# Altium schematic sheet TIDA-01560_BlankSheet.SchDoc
size 431 x 279 mm; Date: Not shown in title block; ApprovedBy: Not shown in title block; CheckedBy: Not shown in title block; Author: Not shown in title block; CompanyName: Not shown in title block; Engineer: Not shown in title block; Organization: Not shown in title block; Address1: Not shown in title block; Address2: Not shown in title block; Address3: Not shown in title block; Address4: Not shown in title block; DocumentNumber: 1; Revision: Use project parameter SCH_Rev; SheetNumber: 2; SheetTotal: 2; PageSetup: Record=PageOptions¦CenterHorizontal=True¦CenterVertical=True¦PrintScale=1.00¦XCorrection=1.00¦YCorrection=1.00¦PrintKind=0¦BorderSize=5000000¦LeftOffset=0¦BottomOffset=0¦Orientation=2¦PaperLength=1000¦PaperWidth=1000¦Scale=100¦PaperSource=15¦PrintQuality=600¦MediaType=1¦DitherType=10¦PaperKind=Letter¦PrintScaleMode=1
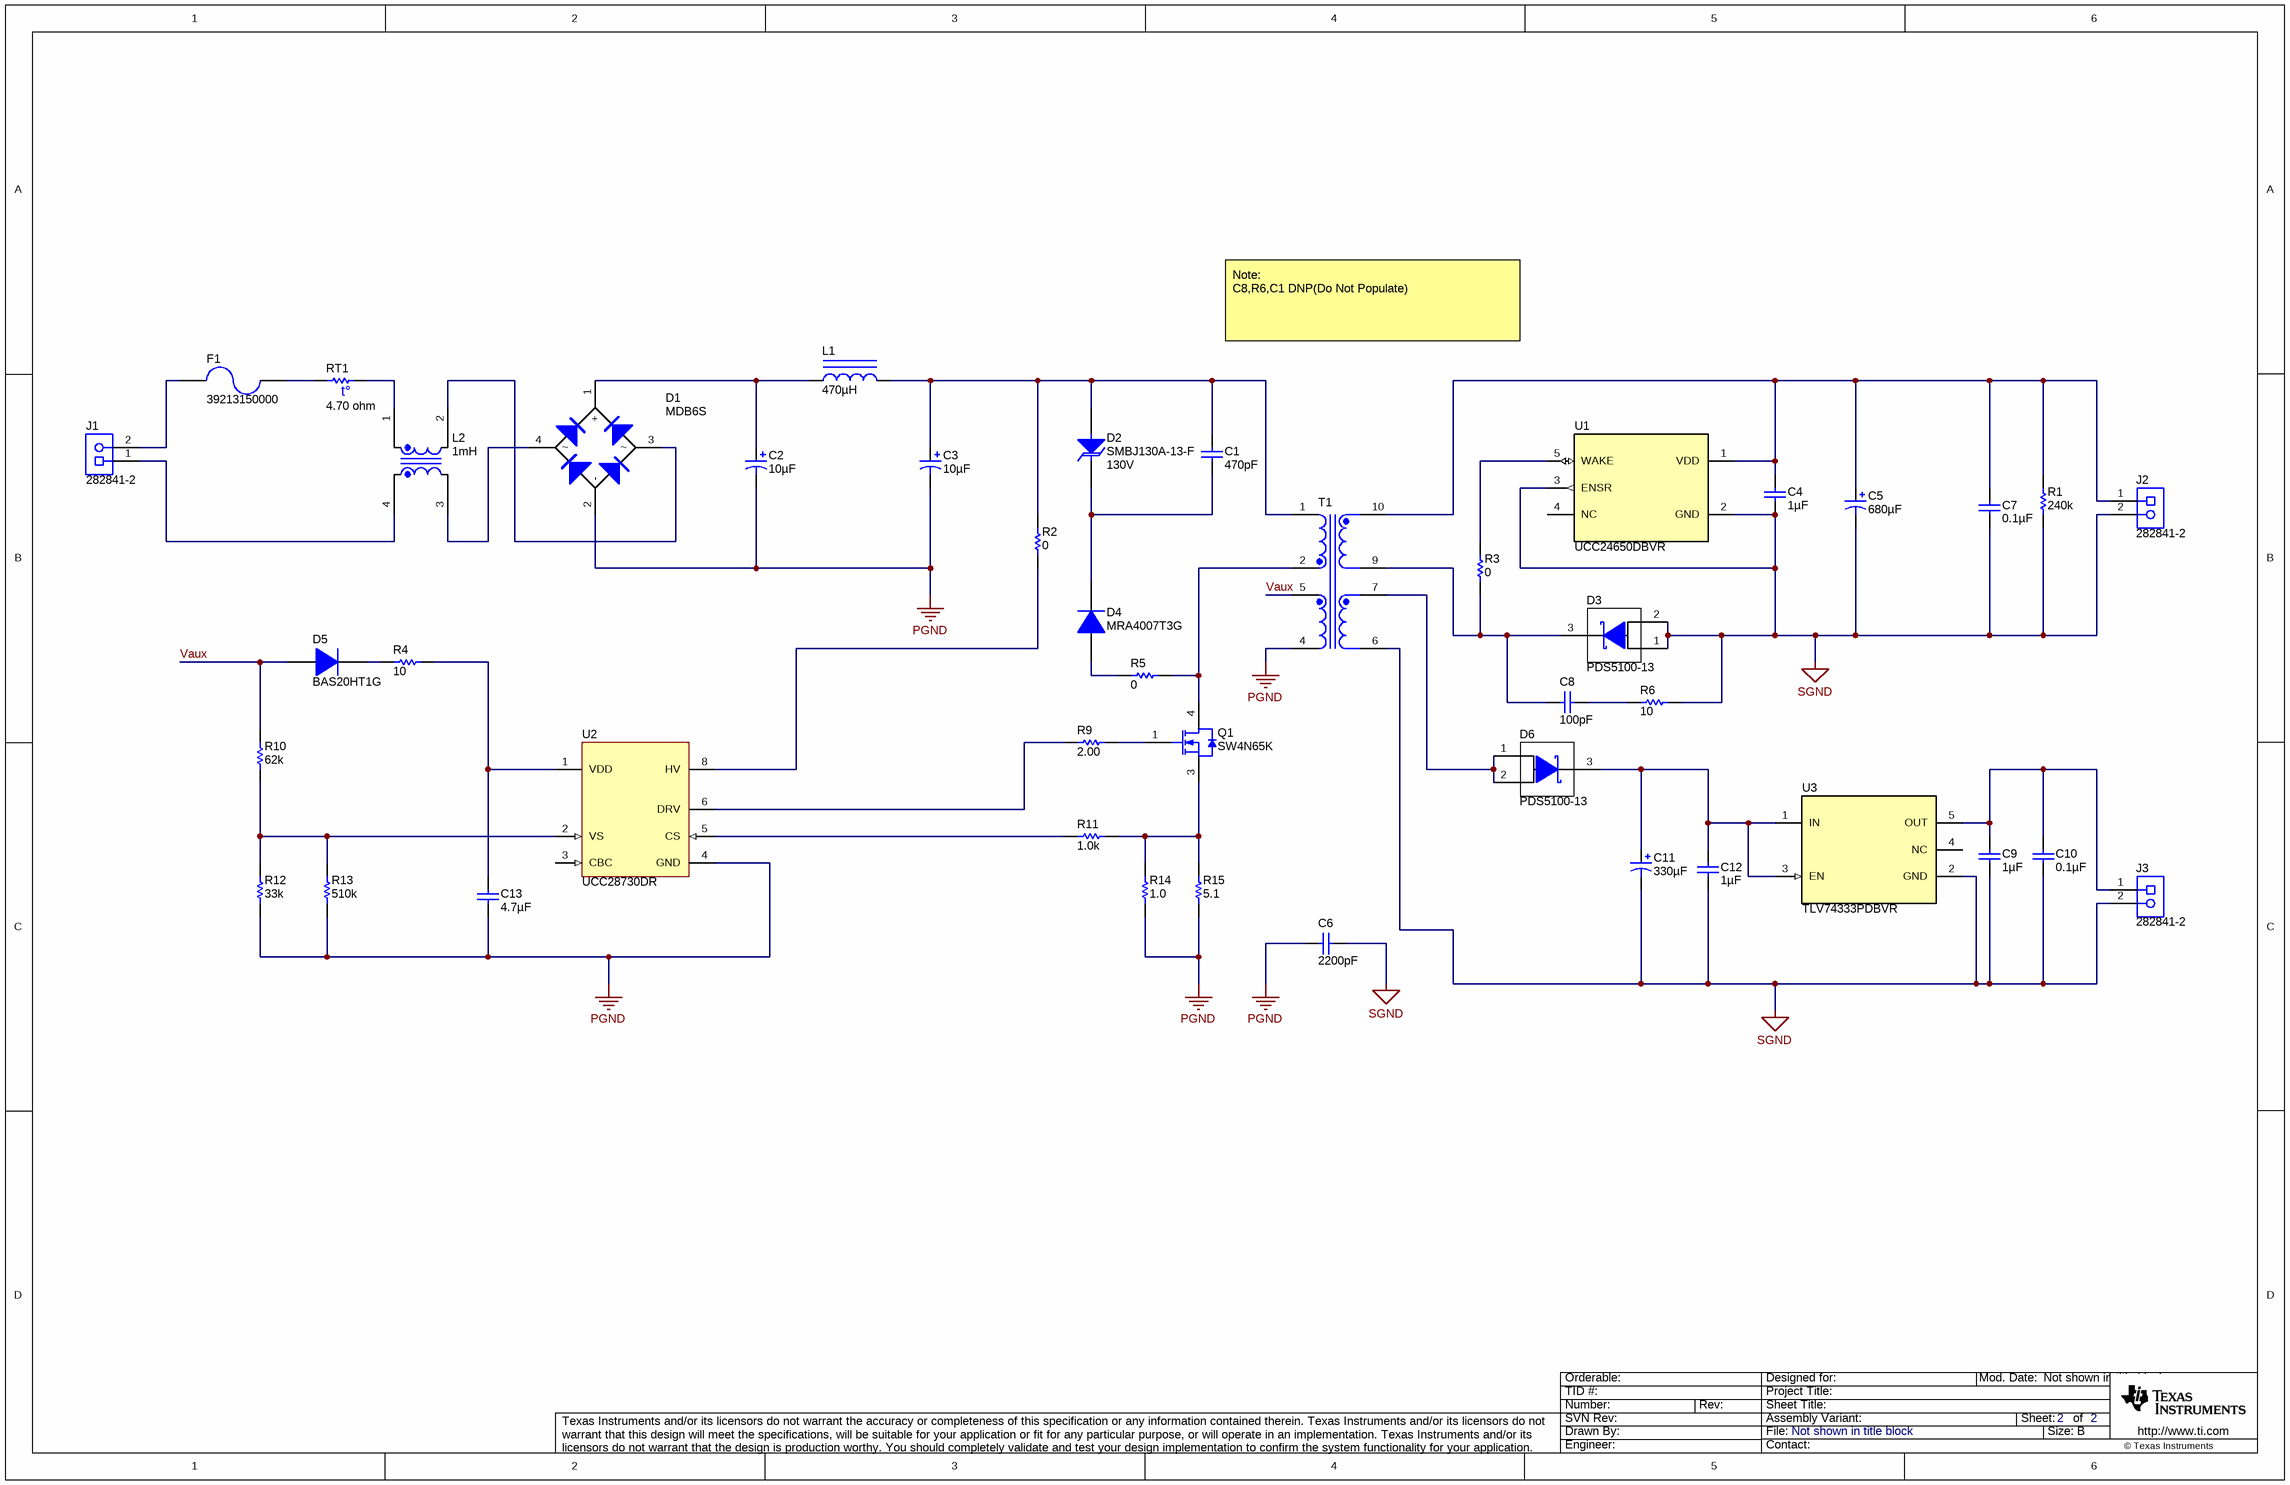
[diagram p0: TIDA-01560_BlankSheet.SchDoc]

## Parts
C1  ValueDisplayed: 470pF  [1206]  (hidden comment: GRM31A7U2J471JW31D)
C2  ValueDisplayed: 10µF  [CY_1000x1600]  (hidden comment: UCY2G100MPD1TD)
C3  ValueDisplayed: 10µF  [CY_1000x1600]  (hidden comment: UCY2G100MPD1TD)
C4  ValueDisplayed: 1µF  [0603]  (hidden comment: 06033C105KAT2A)
C5  ValueDisplayed: 680µF  [R7_1000x1250]  (hidden comment: APSG200ELL681MJB5S)
C6  ValueDisplayed: 2200pF  [KX_1000x800x1400]  (hidden comment: DE1E3KX222MN5AA01)
C7  ValueDisplayed: 0.1µF  [0603]  (hidden comment: C0603C104K3RACTU)
C8  ValueDisplayed: 100pF  [0805_HV]  (hidden comment: GCM2165C2A101JA16D)
C9  ValueDisplayed: 1µF  [0603]  (hidden comment: C1608X7R1E105K080AB)
C10  ValueDisplayed: 0.1µF  [0603]  (hidden comment: C0603C104K3RACTU)
C11  ValueDisplayed: 330µF  [SM_RADIAL_6.3AMM]  (hidden comment: 875105144010)
C12  ValueDisplayed: 1µF  [0603]  (hidden comment: C1608X7R1E105K080AB)
C13  ValueDisplayed: 4.7µF  [1206_180]  (hidden comment: C3216X7R1H475K160AC)
D1  MDB6S  [MICRODIP_4]
D2  SMBJ130A-13-F  value 130V  [SMB]
D3  PDS5100-13  [PowerDI5]
D4  MRA4007T3G  [SMA]
D5  BAS20HT1G  [sod-323]
D6  PDS5100-13  [PowerDI5]
F1  39213150000  [FUSE_392]
J1  282841-2  [TEC_282841-2]
J2  282841-2  [TEC_282841-2]
J3  282841-2  [TEC_282841-2]
L1  ValueDisplayed: 470µH  [WE-TI_5075]  (hidden comment: 7447462471)
L2  ValueDisplayed: 1mH  [WE-CMB_XS]  (hidden comment: 744821201)
Q1  SW4N65K  [TO-252]
R1  ValueDisplayed: 240k  [0805_HV]  (hidden comment: CRCW0805240KJNEA)
R2  ValueDisplayed: 0  [1206]  (hidden comment: CRCW12060000Z0EA)
R3  ValueDisplayed: 0  [0805_HV]  (hidden comment: CRCW08050000Z0EA)
R4  ValueDisplayed: 10  [0805_HV]  (hidden comment: CRCW080510R0JNEA)
R5  ValueDisplayed: 0  [1206]  (hidden comment: CRCW12060000Z0EA)
R6  ValueDisplayed: 10  [1206]  (hidden comment: CRCW120610R0JNEA)
R9  ValueDisplayed: 2.00  [0603]  (hidden comment: CRCW06032R00FKEA)
R10  ValueDisplayed: 62k  [0805_HV]  (hidden comment: CRCW080562K0JNEA)
R11  ValueDisplayed: 1.0k  [0603]  (hidden comment: CRCW06031K00JNEA)
R12  ValueDisplayed: 33k  [0603]  (hidden comment: CRCW060333K0JNEA)
R13  ValueDisplayed: 510k  [0603]  (hidden comment: CRCW0603510KJNEA)
R14  ValueDisplayed: 1.0  [0805_HV]  (hidden comment: CRCW08051R00JNEA)
R15  ValueDisplayed: 5.1  [0805_HV]  (hidden comment: CRCW08055R10JNEA)
RT1  value 4.70 ohm  [S153]  (hidden comment: B57153S0479M051)
T1  750343769,Rev02  [PCBComponent_1]  (value not drawn)
U1  UCC24650DBVR  [DBV0005A_N]
U2  UCC28730DR  [D0007A_N]
U3  TLV74333PDBVR  [DBV0005A_N]

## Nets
PGND: C2.2(-) C3.2(-) C6.2 C13.2 D1.2(-) R12.1 R13.1 R14.1 R15.1 T1.4 U2.4(GND)
SGND: C4.2 C5.2(-) C6.1 C7.2 C9.2 C10.2 C11.2(-) C12.2 D3.1(A) D3.2(A) J2.2 J3.2 R1.1 R6.2 T1.6 U1.2(GND) U1.3(ENSR) U3.2(GND)
Vaux: D5.2(A) R10.1 T1.5
NetC1_1: C1.1 C3.1(+) D2.2(A) L1.2 R2.2 T1.1
NetC1_2: C1.2 D2.1(K) D4.1(K)
NetC2_1: C2.1(+) D1.1(+) L1.1
NetC4_1: C4.1 C5.1(+) C7.1 J2.1 R1.2 T1.10 U1.1(VDD)
NetC8_1: C8.1 R6.1
NetC8_2: C8.2 D3.3(K) R3.1 T1.9
NetC9_1: C9.1 C10.1 J3.1 U3.5(OUT)
NetC11_1: C11.1(+) C12.1 D6.3(K) U3.1(IN) U3.3(EN)
NetC13_1: C13.1 R4.2 U2.1(VDD)
NetD1_3: D1.3 L2.2
NetD1_4: D1.4 L2.3
NetD4_2: D4.2(A) R5.1
NetD5_1: D5.1(K) R4.1
NetD6_1: D6.1(A) D6.2(A) T1.7
NetF1_1: F1.1 RT1.1
NetF1_2: F1.2 J1.2
NetJ1_1: J1.1 L2.4
NetL2_1: L2.1 RT1.2
NetQ1_1: Q1.1(G) R9.2
NetQ1_3: Q1.3(S) R11.2 R14.2 R15.2
NetQ1_4: Q1.4(D) R5.2 T1.2
NetR2_1: R2.1 U2.8(HV)
NetR3_2: R3.2 U1.5(WAKE)
NetR9_1: R9.1 U2.6(DRV)
NetR10_2: R10.2 R12.2 R13.2 U2.2(VS)
NetR11_1: R11.1 U2.5(CS)

Not connected (* = marked no-connect by the designer): U1 4(NC); U2 3(CBC); U3 4(NC)

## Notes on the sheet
- Note:
  C8,R6,C1 DNP(Do Not Populate)

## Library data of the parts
C1 = GRM31A7U2J471JW31D: CAP, CERM, 470 pF, 630 V, +/- 5%, U2J, 1206; Manufacturer: MuRata; Polarized: N; CompType: Capacitor; Value: 470pF; U/M: EA; Cap_F: 0.00000000047; Tolerance_%: 5; Value1: Unknown; VDC_V: 630; Value2: 630V; TaMin_C: -55; TaMax_C: 125; AEC Category: Q200
C2 C3 = UCY2G100MPD1TD: CAP, AL, 10 µF, 400 V, +/- 20%, TH; Manufacturer: Nichicon; Polarized: Y; CompType: Capacitor; Value: 10uF; U/M: EA; Cap_F: 0.00001; Tolerance_%: 20; Value1: Unknown; VDC_V: 400; Value2: 400V; IRMS_A: 0.15; TaMin_C: -40; TaMax_C: 105; Cap_Case: 10x16mm; AEC Category: Q200
C4 = 06033C105KAT2A: CAP, CERM, 1 µF, 25 V,+/- 10%, X7R, 0603; Manufacturer: AVX; Polarized: N; CompType: Capacitor; Value: 1uF; U/M: EA; Cap_F: 0.000001; Tolerance_%: 10; VDC_V: 25; Value2: 25V; TaMin_C: -55; TaMax_C: 125; SizeArea_mm2: 1.28; SizeAreaWB_mm2: 4.68; SizeX_mm: 1.6; SizeY_mm: 0.8; SizeZ_mm: 1; AEC Category: Q200
C5 = RR71C331MDN1: CAP, AL, 680 µF, 20 V, +/- 20%, 0.012 ohm, TH; Manufacturer: Chemi-Con; Polarized: Y; CompType: Capacitor; Value: 680uF; U/M: EA; Cap_F: 0.00033; Tolerance_%: 20; Value1: 0.007 ohm; VDC_V: 16; Value2: 16V; ESR_ohm: 0.007; IRMS_A: 6.1; TaMin_C: -55; TaMax_C: 105; Cap_Case: 10x12.5; SizeAreaWB_mm2: 144; SizeArea_mm2: 100; SizeX_mm: 10; SizeZ_mm: 14; AEC Category: Q200; AEC Qualified: N
C6 = DE1E3KX222MN5AA01: CAP, CERM, 2200 pF, X1 250 VAC/Y1 300 VAC, +/- 20%, E, 10.0x8.0x14.0mm; Manufacturer: MuRata; Polarized: N; CompType: Capacitor; Value: 2200pF; U/M: EA; Cap_F: 0.0000000022; Tolerance_%: 20; TaMin_C: -25; TaMax_C: 85; Cap_Case: 10x8x14mm; SizeArea_mm2: 80; SizeAreaWB_mm2: 120; SizeX_mm: 10; SizeY_mm: 8; SizeZ_mm: 14; AEC Category: Q200; AC_Safety: X1Y1; VAC_X: 250; VAC_Y: 300
C7 C10 = C0603C104K3RACTU: CAP, CERM, 0.1 µF, 25 V,+/- 10%, X7R, 0603; Manufacturer: Kemet; Polarized: N; CompType: Capacitor; Value: 0.1uF; U/M: EA; Cap_F: 0.0000001; Tolerance_%: 10; VDC_V: 25; Value2: 25V; TaMin_C: -55; TaMax_C: 125; SizeArea_mm2: 1.28; SizeAreaWB_mm2: 4.68; SizeX_mm: 1.6; SizeY_mm: 0.8; SizeZ_mm: 1; AEC Category: Q200; Green_Lifecycle: Active; Green_REACh: Passed
C8 = GCM2165C2A101JA16D: CAP, CERM, 100 pF, 100 V,+/- 5%, C0G/NP0, AEC-Q200 Grade 1, 0805; Manufacturer: MuRata; Polarized: N; CompType: Capacitor; Value: 100pF; U/M: EA; Cap_F: 0.0000000001; Tolerance_%: 5; VDC_V: 100; Value2: 100V; TaMin_C: -55; TaMax_C: 105; Cap_Case: 0805; SizeArea_mm2: 2.5; SizeAreaWB_mm2: 6.75; SizeX_mm: 2; SizeY_mm: 1.25; SizeZ_mm: 1.45; AEC Category: Q200; AEC Qualified: Y; AEC Grade: 1
C9 C12 = C1608X7R1E105K080AB: CAP, CERM, 1 µF, 25 V,+/- 10%, X7R, 0603; Manufacturer: TDK; Polarized: N; CompType: Capacitor; Value: 1uF; U/M: EA; Cap_F: 0.000001; Tolerance_%: 10; VDC_V: 25; Value2: 25V; TaMin_C: -55; TaMax_C: 125; SizeArea_mm2: 1.28; SizeAreaWB_mm2: 4.68; SizeX_mm: 1.6; SizeY_mm: 0.8; SizeZ_mm: 1; AEC Category: Q200; Green_Lifecycle: Active; Green_REACh: Passed
C11 = UUD0J221MCL1GS: CAP, AL, 330 µF, 6.3 V, +/- 20%, 0.020 ohm, SMD; Manufacturer: Wurth Elektronik; Polarized: Y; CompType: Capacitor; Value: 330uF; U/M: EA; Cap_F: 0.00022; Tolerance_%: 20; VDC_V: 6.3; Value2: 6.3V; ESR_ohm: 0.44; IRMS_A: 0.23; TaMin_C: -55; TaMax_C: 105; Cap_Case: 6.3x5.8; SizeAreaWB_mm2: 79.98; SizeArea_mm2: 48.18; SizeX_mm: 7.3; SizeY_mm: 6.6; SizeZ_mm: 6; AEC Category: Q200
C13 = C3216X7R1H475K160AC: CAP, CERM, 4.7 µF, 50 V,+/- 10%, X7R, 1206; Manufacturer: TDK; Polarized: N; CompType: Capacitor; Value: 4.7uF; U/M: EA; Cap_F: 0.0000047; Tolerance_%: 10; ESR_ohm: 0.003158; Value1: 0.003158 ohm; VDC_V: 50; Value2: 50V; IRMS_A: 4.08379; TaMin_C: -55; TaMax_C: 125; Cap_Case: 1206; SizeArea_mm2: 5.12; SizeAreaWB_mm2: 10.92; SizeX_mm: 3.2; SizeY_mm: 1.6; SizeZ_mm: 1.8; AEC Category: Q200
D1 = MDB6S: Diode, Switching-Bridge, 600 V, 1 A, MICRODIP_4; Manufacturer: Fairchild Semiconductor; U/M: EA; Vf_V: 1.1; Value: 600V; Value1: 1A; Value2: 1.1V; Io_A: 1; Vr_V: 600; TJmax_C: 150; SizeAreaWB_mm2: 59.5; SizeArea_mm2: 32.5; SizeX_mm: 6.5; SizeY_mm: 5; SizeZ_mm: 1.45; AEC Category: Q101; Green_Lifecycle: Not Set; Green_REACh: Incomplete
D2 = SMBJ130A-13-F: Diode, TVS, Uni, 130 V, 209 Vc, SMB; Manufacturer: Diodes Inc.; U/M: EA; Power_W: 5; Vr_V: 130; Value1: 5W; SizeAreaWB_mm2: 44.156; SizeArea_mm2: 21.336; SizeX_mm: 5.6; SizeY_mm: 3.81; SizeZ_mm: 2.6; AEC Category: Q101; Green_Lifecycle: Active; Green_REACh: Passed
D3 D6 = PDS5100-13: Diode, Schottky, 100 V, 5 A, PowerDI5; Manufacturer: Diodes Inc.; U/M: EA; Vf_V: 0.79; Value: 100V; Value1: 5A; Value2: 0.79V; Io_A: 5; Vr_V: 100; TJmax_C: 150; SizeAreaWB_mm2: 49.56; SizeArea_mm2: 24.96; SizeX_mm: 6.4; SizeY_mm: 3.9; SizeZ_mm: 1.05; AEC Category: Q101; Green_Lifecycle: Not Set; Green_REACh: Incomplete
D4 = MRA4007T3G: Diode, Standard Recovery Rectifier, 1000 V, 1 A, AEC-Q101, SMA; Manufacturer: ON Semiconductor; U/M: EA; Vf_V: 1.1; Value: 1000V; Value1: 1A; Value2: 1.1V; Io_A: 1; Vr_V: 1000; TJmax_C: 175; RJC_CperW: 16.2; SizeAreaWB_mm2: 37.3428; SizeArea_mm2: 16.3228; SizeX_mm: 5.59; SizeY_mm: 2.92; SizeZ_mm: 2.87; AEC Category: Q101; AEC Qualified: Y; Green_Lifecycle: Active; Green_REACh: Passed
D5 = BAS20HT1G: Diode, Switching, 200 V, 0.2 A, AEC-Q101, SOD-323; Manufacturer: ON Semiconductor; U/M: EA; Vf_V: 1.25; Value: 200V; Value1: 0.2A; Value2: 1.25V; Io_A: 0.2; Vr_V: 200; TJmax_C: 150; AEC Category: Q101; AEC Qualified: Y
F1 = 39213150000: Fuse, 3.15 A, 250VAC/VDC, TH; Manufacturer: Littelfuse; VDC_V: 250; Irating_A: 3.15
J1-J3 = 282841-2: Terminal Block, 2x1, 5.08mm, TH; Manufacturer: TE Connectivity; SymbolCreator: a0412235
L1 = 7447462471: Inductor, Unshielded Drum Core, Ferrite, 470 µH, 0.35 A, 1.58 ohm, TH; Manufacturer: Wurth Elektronik; Value: 470uH; Ind_H: 470.0E-6; Imax_A: 0.35; Irms: 0.35A @ 40C rise; Isat: 0.4A @ 10% inductance drop; DCR_ohm: 1.58; Value2: 0.35A; SizeAreaWB_mm2: 64; SizeArea_mm2: 36; SizeX_mm: 6; SizeZ_mm: 8.5; AEC Category: Q200; Green_Lifecycle: Active; Green_REACh: Passed
L2 = 744821201: Coupled inductor, 1 mH, 2 A, 0.045 ohm, TH; Manufacturer: Wurth Elektronik; SymbolCreator: a0412235; Value: 1mH; Ind_H: 1.0E-3; DCR_ohm: 0.045
Q1 = IXTY02N120P: MOSFET, N-CH, 650 V, 4 A, TO-252; Manufacturer: IXYS; Alternate Manufacturer: None; U/M: EA; ChType: N; Value: 650V; VdsMax_V: 1200; Value1: ? ohm; Value2: 4.7 nC; QgTyp_nC: 4.7; Vgs_V: 20; IdsMax_A: 0.2; SizeAreaWB_mm2: 79.794; SizeArea_mm2: 48.034; SizeX_mm: 6.58; SizeY_mm: 7.3; SizeZ_mm: 2.3; AEC Category: Q101; Green_Lifecycle: Not Set; Green_REACh: Incomplete
R1 = CRCW0805240KJNEA: RES, 240 k, 5%, 0.125 W, 0805; Manufacturer: Vishay-Dale; CompType: Resistor; Value: 240k; Res_ohm: 240000; Tolerance_%: 5; Power_W: 0.125; Value2: 0.125W; VDC_V: 150; TempCo: 200 ppm/C; EIA_Code: E24; U/M: EA; AEC Category: Q200; SizeArea_mm2: 2.5; SizeX_mm: 2; SizeY_mm: 1.25; SizeZ_mm: 1.45
R2 R5 = CRCW12060000Z0EA: RES, 0, 5%, 0.25 W, 1206; Manufacturer: Vishay-Dale; CompType: Resistor; Value: 0; Value_Code: 0000; Tolerance_%: 5; Power_W: 0.25; Value2: 0.25W; VDC_V: 200; TempCo: 200 ppm/C; SizeArea_mm2: 5.12; SizeX_mm: 3.2; SizeY_mm: 1.6; SizeZ_mm: 1.35; EIA_Code: E24; U/M: EA; AEC Category: Q200; Green_Lifecycle: Active; Green_REACh: Passed
R3 = CRCW08050000Z0EA: RES, 0, 5%, 0.125 W, 0805; Manufacturer: Vishay-Dale; CompType: Resistor; Value: 0; Value_Code: 0000; Tolerance_%: 5; Power_W: 0.125; Value2: 0.125W; VDC_V: 150; TempCo: 200 ppm/C; SizeArea_mm2: 2.5; SizeX_mm: 2; SizeY_mm: 1.25; SizeZ_mm: 1.45; EIA_Code: E24; U/M: EA; AEC Category: Q200; Green_Lifecycle: Active; Green_REACh: Passed
R4 = CRCW080510R0JNEA: RES, 10, 5%, 0.125 W, 0805; Manufacturer: Vishay-Dale; CompType: Resistor; Value: 10; Value_Code: 10R0; Tolerance_%: 5; Power_W: 0.125; Value2: 0.125W; VDC_V: 150; TempCo: 200 ppm/C; EIA_Code: E24; U/M: EA; AEC Category: Q200; SizeArea_mm2: 2.5; SizeX_mm: 2; SizeY_mm: 1.25; SizeZ_mm: 1.45; Green_Lifecycle: Active; Green_REACh: Passed
R6 = CRCW120610R0JNEA: RES, 10, 5%, 0.25 W, 1206; Manufacturer: Vishay-Dale; CompType: Resistor; Value: 10; Value_Code: 10R0; Tolerance_%: 5; Power_W: 0.25; Value2: 0.25W; VDC_V: 200; TempCo: 200 ppm/C; EIA_Code: E24; U/M: EA; AEC Category: Q200
R9 = CRCW06032R00FKEA: RES, 2.00, 1%, 0.1 W, 0603; Manufacturer: Vishay-Dale; CompType: Resistor; Value: 2.00; Res_ohm: 2; Value_Code: 2R00; Tolerance_%: 1; Power_W: 0.1; Value2: 0.1W; VDC_V: 75; TempCo: 100 ppm/C; EIA_Code: E96; U/M: EA; AEC Category: Q200
R10 = CRCW080562K0JNEA: RES, 62 k, 5%, 0.125 W, 0805; Manufacturer: Vishay-Dale; CompType: Resistor; Value: 62k; Res_ohm: 62000; Value_Code: 62k0; Tolerance_%: 5; Power_W: 0.125; Value2: 0.125W; VDC_V: 150; TempCo: 200 ppm/C; EIA_Code: E24; U/M: EA; AEC Category: Q200; SizeArea_mm2: 2.5; SizeX_mm: 2; SizeY_mm: 1.25; SizeZ_mm: 1.45
R11 = CRCW06031K00JNEA: RES, 1.0 k, 5%, 0.1 W, 0603; Manufacturer: Vishay-Dale; CompType: Resistor; Value: 1.0k; Res_ohm: 1000; Value_Code: 1k00; Tolerance_%: 5; Power_W: 0.1; Value2: 0.1W; VDC_V: 75; TempCo: 200 ppm/C; EIA_Code: E24; U/M: EA; AEC Category: Q200; SizeArea_mm2: 1.28; SizeX_mm: 1.6; SizeY_mm: 0.8; SizeZ_mm: 1; Green_Lifecycle: Active; Green_REACh: Passed
R12 = CRCW060333K0JNEA: RES, 33 k, 5%, 0.1 W, 0603; Manufacturer: Vishay-Dale; CompType: Resistor; Value: 33k; Res_ohm: 33000; Value_Code: 33k0; Tolerance_%: 5; Power_W: 0.1; Value2: 0.1W; VDC_V: 75; TempCo: 200 ppm/C; EIA_Code: E24; U/M: EA; AEC Category: Q200; SizeArea_mm2: 1.28; SizeX_mm: 1.6; SizeY_mm: 0.8; SizeZ_mm: 1; Green_Lifecycle: Active; Green_REACh: Passed
R13 = CRCW0603510KJNEA: RES, 510 k, 5%, 0.1 W, 0603; Manufacturer: Vishay-Dale; CompType: Resistor; Value: 510k; Res_ohm: 510000; Tolerance_%: 5; Power_W: 0.1; Value2: 0.1W; VDC_V: 75; TempCo: 200 ppm/C; EIA_Code: E24; U/M: EA; AEC Category: Q200; SizeArea_mm2: 1.28; SizeX_mm: 1.6; SizeY_mm: 0.8; SizeZ_mm: 1; Green_Lifecycle: Active; Green_REACh: Passed
R14 = CRCW08051R00JNEA: RES, 1.0, 5%, 0.125 W, 0805; Manufacturer: Vishay-Dale; CompType: Resistor; Value: 1.0; Res_ohm: 1; Value_Code: 1R00; Tolerance_%: 5; Power_W: 0.125; Value2: 0.125W; VDC_V: 150; TempCo: 200 ppm/C; SizeArea_mm2: 2.5; SizeX_mm: 2; SizeY_mm: 1.25; SizeZ_mm: 1.45; EIA_Code: E24; U/M: EA; AEC Category: Q200; Green_Lifecycle: Active; Green_REACh: Passed
R15 = CRCW08055R10JNEA: RES, 5.1, 5%, 0.125 W, 0805; Manufacturer: Vishay-Dale; CompType: Resistor; Value: 5.1; Value_Code: 5R10; Tolerance_%: 5; Power_W: 0.125; Value2: 0.125W; VDC_V: 150; TempCo: 200 ppm/C; SizeArea_mm2: 2.5; SizeX_mm: 2; SizeY_mm: 1.25; SizeZ_mm: 1.45; EIA_Code: E24; U/M: EA; AEC Category: Q200
RT1 = B57153S0479M051: Thermistor NTC, 4.70 ohm, 20%, 8.5mm Disc; Manufacturer: TDK; Tolerance_%: 20; Power_W: 1.4; TaMin_C: -55; TaMax_C: 170; U/M: EA
T1 = Component_1: Transformer, 620uH, TH; Manufacturer: Wurth Elektronik; SymbolVersion: use current date i.e. 2008-05-20; SymbolCreator: Use a-id; CompType: Used in some BOM reports.  Useful for finding later.; U/M: EA, IN, or GM
U1 = UCC24650DBVR: 200-V Wake-Up Monitor for Fast Transient PSR, DBV0005A; Alternate PartNumber: UCC24650DBVT; Manufacturer: Texas Instruments; SymbolCreator: x0208326; CompType: IC; U/M: EA
U2 = UCC28730DR: Constant-Voltage Constant-Current Flyback Controller With PSR and Wake-Up Monitoring, D0007A; Manufacturer: Texas Instruments; SymbolCreator: x0208325; CompType: IC; U/M: EA
U3 = TLV74333PDBVR: Low-Dropout Regulator, DBV0005A (SOT-23-5); Manufacturer: Texas Instruments; SymbolCreator: Altium; SizeArea_mm2: 8.12; SizeAreaWB_mm2: 14.82; SizeX_mm: 2.8; SizeY_mm: 2.9; SizeZ_mm: 1.45; CompType: IC; U/M: EA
